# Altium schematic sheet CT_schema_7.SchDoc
size 277 x 170 mm
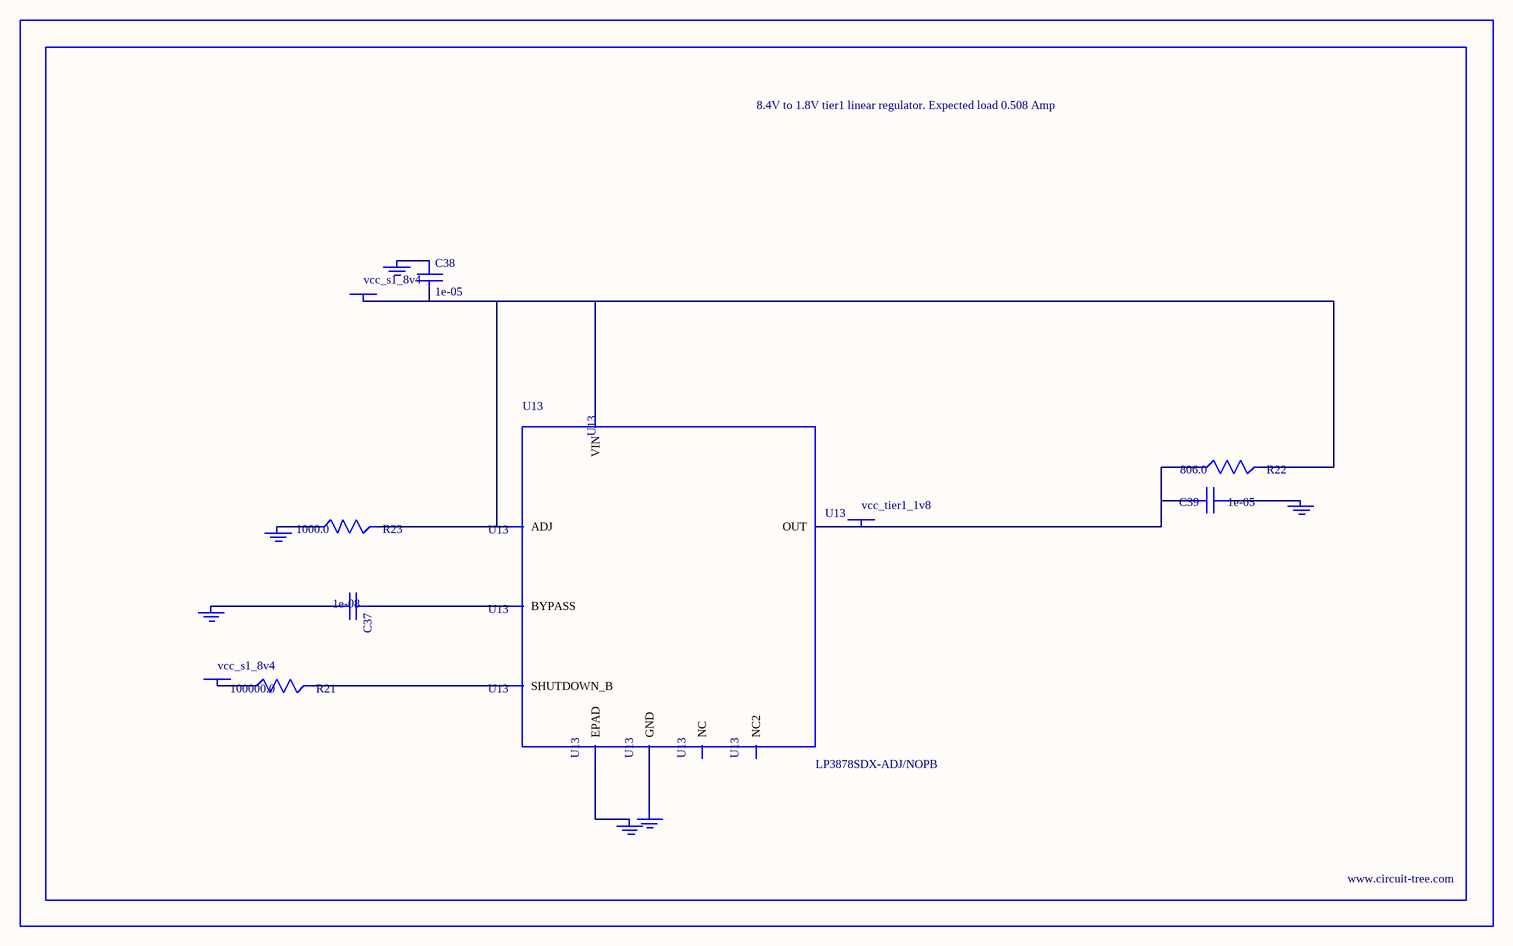
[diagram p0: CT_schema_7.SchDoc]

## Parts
BORDER6  (no value)
C37  1e-08  [C0402]
C38  1e-05  [C1206]
C39  1e-05  [C0805]
GND_INSTANCE_6_0  (no value)
GND_INSTANCE_6_1  (no value)
GND_INSTANCE_6_2  (no value)
GND_INSTANCE_6_3  (no value)
GND_INSTANCE_6_4  (no value)
GND_INSTANCE_6_5  (no value)
POWER_INSTANCE_6_0  vcc_s1_8v4
POWER_INSTANCE_6_1  vcc_s1_8v4
POWER_INSTANCE_6_2  vcc_tier1_1v8
R21  100000.0  [R0603]
R22  806.0  [R0603]
R23  1000.0  [R0603]
U13  LP3878SDX-ADJ/NOPB  [WSON-8]

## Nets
NetC37_1: C37.1 U13.1(BYPASS)
NetC37_2: C37.2 GND_INSTANCE_6_0.0(GND)
NetC38_1: C38.1 GND_INSTANCE_6_1.0(GND)
NetC38_2: C38.2 POWER_INSTANCE_6_0.0(PWR) R22.2 R23.2 U13.4(VIN) U13.6(ADJ)
NetC39_1: C39.1 GND_INSTANCE_6_2.0(GND)
NetC39_2: C39.2 POWER_INSTANCE_6_2.0(PWR) R22.1 U13.5(OUT)
NetGND_INSTANCE_6_3_0: GND_INSTANCE_6_3.0(GND) R23.1
NetGND_INSTANCE_6_4_0: GND_INSTANCE_6_4.0(GND) U13.PAD(EPAD)
NetGND_INSTANCE_6_5_0: GND_INSTANCE_6_5.0(GND) U13.3(GND)
NetPOWER_INSTANCE_6_1_0: POWER_INSTANCE_6_1.0(PWR) R21.1
NetR21_2: R21.2 U13.8(SHUTDOWN_B)

Not connected (* = marked no-connect by the designer): U13 2(NC) 7(NC2)

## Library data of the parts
BORDER6 = BORDER_PAGE6
C37 = C0402C103K3RAC
C38 = C1206C106K3RACTU
C39 = GRM219R60J106ME19D
GND_INSTANCE_6_0-GND_INSTANCE_6_5 = GND
POWER_INSTANCE_6_0-POWER_INSTANCE_6_2 = PWR
R21 = RC0603JR-07100KL
R22 = ERJ-3EKF8060V
R23 = RC0603JR-071KL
